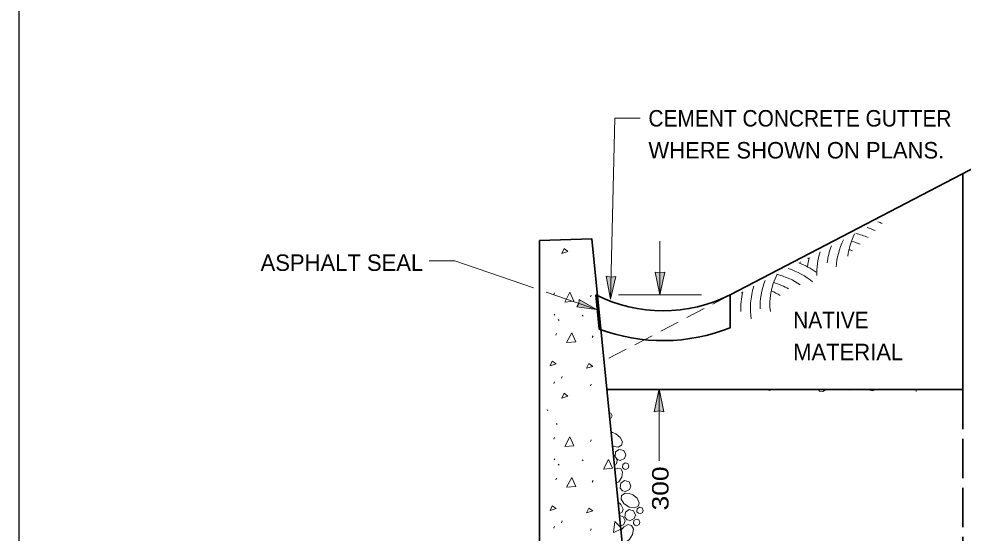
# Model space of a CAD drawing. Extents: x 17672 to 18472, y -9785 to -9267.
# Drawn here: x 17671.8 to 17874.3, y -9636.2 to -9525.9 of the extents above; entities that cross this region are included whole.
import ezdxf

# ---------------------------------------------------------------- set-up
doc = ezdxf.new("R2010")
doc.units = 0
doc.header["$LTSCALE"] = 1.4
doc.linetypes.add('LONG_DASHED', pattern=[7.5, 6, -1.5])
doc.linetypes.add('MEDIUM_DASHED', pattern=[4.5, 3, -1.5])
for name, color, linetype, lineweight in [('1', 7, 'Continuous', 13), ('15', 7, 'Continuous', 13), ('16', 7, 'Continuous', 13), ('20', 7, 'Continuous', 25), ('30', 7, 'Continuous', 25)]:
    doc.layers.add(name, color=color, linetype=linetype, lineweight=lineweight)
doc.layers.add('19', color=7, linetype='Continuous')

msp = doc.modelspace()

# ---------------------------------------------------------------- hatches: boundary and pattern name
at = {"layer": '16'}
for points in [[(17809.268, -9585.103), (17810.297, -9580.201), (17809.268, -9580.397), (17808.239, -9580.201)], [(17798.685, -9586.03), (17799.824, -9581.152), (17798.79, -9581.326), (17797.765, -9581.106)], [(17795.631, -9588.196), (17791.974, -9586.11), (17791.893, -9586.91), (17791.452, -9587.625)], [(17809.065, -9605.255), (17808.035, -9610.157), (17809.065, -9609.961), (17810.094, -9610.157)]]:
    msp.add_hatch(color=256, dxfattribs=at).paths.add_polyline_path(points)

# ---------------------------------------------------------------- linework, layer by layer
at = {"layer": '1', "lineweight": 35}
for p, q in [((17921.042, -9534.724), (17824.355, -9585.104)), ((17874.195, -9605.385), (17874.195, -9559.134)), ((17795.493, -9585.104), (17796.228, -9592.414)), ((17824.355, -9592.127), (17824.355, -9585.104)), ((17797.869, -9605.385), (17874.195, -9605.385))]:
    msp.add_line(p, q, dxfattribs=at)
at = {"layer": '1'}
for p, q in [((17786.513, -9585.003), (17786.67, -9584.63)), ((17794.359, -9585.515), (17794.513, -9585.157)), ((17786.559, -9589.196), (17786.731, -9589.461)), ((17787.444, -9590.361), (17787.616, -9590.611)), ((17792.618, -9589.414), (17792.787, -9589.662)), ((17786.903, -9593.716), (17787.057, -9593.343)), ((17794.761, -9594.228), (17794.917, -9593.856)), ((17788.145, -9602.927), (17788.314, -9602.554)), ((17786.498, -9604.062), (17786.653, -9603.704)), ((17794.341, -9604.589), (17794.498, -9604.233)), ((17797.873, -9605.432), (17797.882, -9605.426)), ((17839.864, -9605.385), (17839.952, -9605.42)), ((17849.812, -9605.532), (17849.928, -9605.385)), ((17864.204, -9605.777), (17864.24, -9605.385)), ((17785.084, -9609.67), (17785.256, -9609.917)), ((17787.057, -9612.65), (17787.229, -9612.9)), ((17786.513, -9616.005), (17786.67, -9615.633)), ((17794.359, -9616.518), (17794.513, -9616.162)), ((17786.559, -9620.199), (17786.731, -9620.464)), ((17787.444, -9621.366), (17787.616, -9621.613)), ((17792.618, -9620.417), (17792.787, -9620.667)), ((17786.903, -9624.721), (17787.057, -9624.349)), ((17794.761, -9625.233), (17794.917, -9624.861)), ((17788.145, -9633.932), (17788.314, -9633.559)), ((17786.498, -9635.064), (17786.653, -9634.709)), ((17794.341, -9635.594), (17794.498, -9635.236)), ((17800.861, -9635.302), (17799.344, -9636.013))]:
    msp.add_line(p, q, dxfattribs=at)
at = {"layer": '1', "linetype": 'MEDIUM_DASHED'}
msp.add_line((17824.355, -9585.104), (17796.88, -9599.42), dxfattribs=at)
at = {"layer": '1', "linetype": 'LONG_DASHED', "lineweight": 35}
msp.add_line((17874.195, -9708.364), (17874.195, -9605.385), dxfattribs=at)
at = {"layer": '1', "lineweight": 35}
msp.add_lwpolyline([(17783.439, -9705.506), (17783.439, -9573.439), (17794.636, -9573.056), (17807.886, -9705.526), (17783.439, -9705.526)], close=True, dxfattribs=at)
at = {"layer": '1'}
for points in [[(17788.221, -9576.194), (17788.719, -9575.169), (17789.528, -9575.792)], [(17785.689, -9600.302), (17786.172, -9599.277), (17786.996, -9599.883)], [(17793.535, -9600.814), (17794.015, -9599.79), (17794.839, -9600.41)], [(17788.221, -9607.199), (17788.719, -9606.174), (17789.528, -9606.794)], [(17799.633, -9619.818), (17799.728, -9618.748), (17800.555, -9618.206), (17801.504, -9618.479), (17801.916, -9619.391), (17801.642, -9620.135), (17800.763, -9620.562), (17800.144, -9620.406)], [(17801.254, -9622.063), (17801.311, -9621.421), (17801.807, -9621.096), (17802.376, -9621.26), (17802.624, -9621.807), (17802.459, -9622.253), (17801.932, -9622.509), (17801.561, -9622.415)], [(17785.689, -9631.307), (17786.172, -9630.282), (17786.996, -9630.888)], [(17793.535, -9631.819), (17794.015, -9630.795), (17794.839, -9631.415)], [(17801.758, -9632.734), (17801.853, -9631.664), (17802.679, -9631.121), (17803.629, -9631.394), (17804.041, -9632.307), (17803.767, -9633.051), (17802.888, -9633.476), (17802.269, -9633.321)], [(17804.329, -9631.563), (17804.386, -9630.921), (17804.882, -9630.596), (17805.451, -9630.76), (17805.698, -9631.307), (17805.534, -9631.753), (17805.007, -9632.009), (17804.635, -9631.915)]]:
    msp.add_lwpolyline(points, close=True, dxfattribs=at)
for points in [[(17788.844, -9586.618), (17789.947, -9584.537), (17790.817, -9586.461), (17788.89, -9586.618)], [(17789.248, -9595.331), (17790.351, -9593.25), (17791.204, -9595.16), (17789.278, -9595.331)], [(17798.01, -9606.792), (17798.145, -9607.091), (17798.062, -9607.316)], [(17833.286, -9605.385), (17832.857, -9605.593), (17832.238, -9605.438), (17832.193, -9605.385)], [(17836.599, -9605.385), (17836.466, -9605.449), (17836.212, -9605.385)], [(17844.905, -9605.385), (17844.235, -9605.788), (17843.468, -9605.715), (17843.247, -9605.385)], [(17855.476, -9605.385), (17854.904, -9605.663), (17854.285, -9605.507), (17854.179, -9605.385)], [(17798.365, -9610.346), (17798.749, -9610.457), (17798.997, -9611.004), (17798.832, -9611.45), (17798.492, -9611.615)], [(17798.791, -9614.604), (17799.138, -9614.62), (17799.833, -9614.893)], [(17799.784, -9614.867), (17800.759, -9615.639), (17801.21, -9616.605), (17801.047, -9617.282), (17800.292, -9617.699), (17799.083, -9617.528)], [(17788.844, -9617.621), (17789.947, -9615.54), (17790.817, -9617.466), (17788.89, -9617.621)], [(17799.264, -9619.332), (17799.656, -9619.643), (17800.107, -9620.608), (17799.944, -9621.285), (17799.484, -9621.539)], [(17797.153, -9622.437), (17798.256, -9620.356), (17799.111, -9622.265), (17797.199, -9622.437)], [(17799.583, -9622.523), (17800.242, -9622.215), (17800.851, -9622.362), (17801.227, -9623.04), (17801.071, -9624.148), (17800.414, -9625.142), (17799.877, -9625.465)], [(17789.248, -9626.336), (17790.351, -9624.255), (17791.204, -9626.165), (17789.278, -9626.336)], [(17800.758, -9626.507), (17800.854, -9625.437), (17801.68, -9624.894), (17802.629, -9625.168), (17803.041, -9626.08), (17802.767, -9626.824), (17801.888, -9627.249), (17801.269, -9627.094), (17800.759, -9626.507)], [(17800.284, -9629.537), (17800.904, -9630.027), (17801.355, -9630.993), (17801.192, -9631.67), (17800.534, -9632.033)], [(17803.382, -9627.909), (17804.356, -9628.681), (17804.808, -9629.646), (17804.645, -9630.323), (17803.891, -9630.74), (17802.659, -9630.567), (17801.555, -9629.837), (17800.981, -9628.881), (17801.053, -9628.114), (17801.793, -9627.618), (17802.736, -9627.662), (17803.431, -9627.934)], [(17800.57, -9632.392), (17801.409, -9632.633), (17801.821, -9633.545), (17801.547, -9634.289), (17800.796, -9634.653)], [(17803.599, -9634.126), (17803.657, -9633.483), (17804.152, -9633.158), (17804.722, -9633.322), (17804.97, -9633.869), (17804.805, -9634.316), (17804.277, -9634.571), (17803.906, -9634.477), (17803.6, -9634.125)], [(17799.312, -9636.013), (17799.623, -9633.682), (17800.822, -9634.907)], [(17800.887, -9635.563), (17801.503, -9634.785), (17802.469, -9634.334), (17803.146, -9634.497), (17803.563, -9635.251), (17803.389, -9636.483), (17802.66, -9637.587), (17801.703, -9638.162), (17801.142, -9638.109)]]:
    msp.add_lwpolyline(points, dxfattribs=at)
at = {"layer": '1', "lineweight": 35}
for centre, radius, start, end in [((17809.924, -9556.124), 32.374, 243.52748, 296.47252), ((17809.922, -9555.905), 38.992, 249.44043, 291.72582)]:
    msp.add_arc(centre, radius, start, end, dxfattribs=at)
at = {"layer": '1'}
for centre, major_axis, start_param, end_param in [((17840.44, -9588.774), (21.721, 11.27), 0.5089521, 0.6048262), ((17840.44, -9588.774), (23.677, 12.286), 0.5035044, 0.5487601), ((17868.436, -9574.247), (-17.807, -9.24), 5.5176695, 5.8182486), ((17840.44, -9588.774), (19.764, 10.255), 0.5214974, 0.6750191), ((17866.083, -9575.468), (-19.764, -10.255), 5.6081662, 5.8162629), ((17866.083, -9575.468), (-17.807, -9.24), 5.5176695, 5.890171), ((17840.44, -9588.774), (17.807, 9.24), 0.545492, 0.6663322), ((17866.083, -9575.468), (-21.721, -11.27), 5.6783592, 5.9462814), ((17838.284, -9589.971), (17.807, 9.24), 0.5121332, 0.5623339), ((17823.498, -9597.565), (23.677, 12.286), 0.3472839, 0.5487601), ((17814.35, -9575.552), (25.27, 13.112), 5.5360053, 5.5474825), ((17866.083, -9575.468), (-23.677, -12.286), 5.7344252, 5.8300808), ((17853.352, -9555.315), (-25.27, -13.112), 0.7357028, 0.74718), ((17851.851, -9582.853), (-17.807, -9.24), 5.5176695, 6.0355169), ((17823.498, -9597.565), (19.764, 10.255), 0.3642278, 0.6750191), ((17823.498, -9597.565), (21.721, 11.27), 0.2884398, 0.6048262), ((17851.851, -9582.853), (-19.764, -10.255), 5.6081662, 5.9621663), ((17823.498, -9597.565), (17.807, 9.24), 0.4330369, 0.6499807), ((17851.851, -9582.853), (-23.677, -12.286), 5.7344252, 5.9365445), ((17839.12, -9562.7), (-25.27, -13.112), 0.7357028, 0.74718), ((17851.851, -9582.853), (-21.721, -11.27), 5.6783592, 6.0528283), ((17821.342, -9598.761), (17.807, 9.24), 0.4054458, 0.5431634)]:
    msp.add_ellipse(centre, major_axis=major_axis, ratio=0.719298, start_param=start_param, end_param=end_param, dxfattribs=at)
at = {"layer": '15'}
for p, q in [((17809.267, -9585.104), (17809.267, -9573.56)), ((17784.868, -9584.493), (17795.631, -9588.196)), ((17800.35, -9585.104), (17818.185, -9585.104)), ((17809.064, -9620.659), (17809.064, -9605.256))]:
    msp.add_line(p, q, dxfattribs=at)
msp.add_lwpolyline([(17759.738, -9577.755), (17765.292, -9577.755), (17782.157, -9583.559)], dxfattribs=at)
at = {"layer": '16'}
for points in [[(17809.268, -9585.103), (17810.297, -9580.201), (17809.268, -9580.397), (17808.239, -9580.201)], [(17798.685, -9586.03), (17799.824, -9581.152), (17798.79, -9581.326), (17797.765, -9581.106)], [(17795.631, -9588.196), (17791.974, -9586.11), (17791.893, -9586.91), (17791.452, -9587.625)], [(17809.065, -9605.255), (17808.035, -9610.157), (17809.065, -9609.961), (17810.094, -9610.157)]]:
    msp.add_lwpolyline(points, close=True, dxfattribs=at)
at = {"layer": '20', "lineweight": 13}
msp.add_lwpolyline([(17805.041, -9547.221), (17799.561, -9547.221), (17798.684, -9586.03)], dxfattribs=at)
at = {"layer": '30'}
msp.add_line((17671.774, -9267.105), (17671.774, -9784.752), dxfattribs=at)

# ---------------------------------------------------------------- texts
at = {"layer": '19', "width": 1.2}
msp.add_text('300', height=3.529, rotation=90, dxfattribs=at).set_placement((17811.106, -9631.309))
at = {"layer": '20', "width": 0.95}
for s, p in [('CEMENT CONCRETE GUTTER', (17806.792, -9549)), ('NATIVE', (17837.839, -9592.243))]:
    msp.add_text(s, height=3.529, dxfattribs=at).set_placement(p)
at = {"layer": '20'}
for s, p in [('WHERE SHOWN ON PLANS.', (17806.792, -9555.85)), ('ASPHALT SEAL', (17723.61, -9579.946)), ('MATERIAL', (17837.839, -9599.093))]:
    msp.add_text(s, height=3.529, dxfattribs=at).set_placement(p)

doc.saveas('drawing.dxf')
